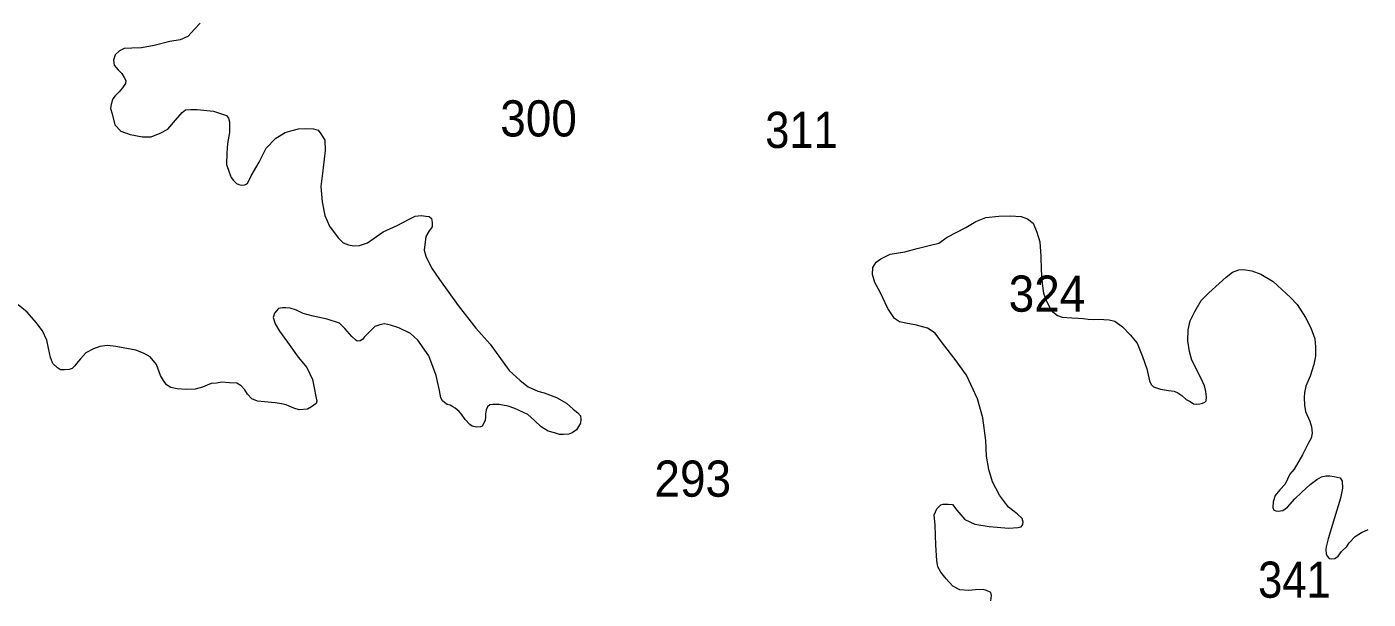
# Model space of a CAD drawing. Extents: x 445.4 to 500, y 8728.7 to 8784.
# Drawn here: x 494.06 to 500, y 8752.65 to 8755.18 of the extents above; entities that cross this region are included whole.
import ezdxf

# ---------------------------------------------------------------- set-up
doc = ezdxf.new("R2010")
doc.units = 0
doc.header["$LTSCALE"] = 0.064
doc.layers.add('2', color=7, linetype='Continuous', lineweight=13)
doc.layers.add('21', color=7, linetype='Continuous')

msp = doc.modelspace()

# ---------------------------------------------------------------- linework, layer by layer
at = {"layer": '2'}
for points in [[(494.8312, 8755.1948), (494.8068, 8755.1685), (494.7766, 8755.1365), (494.7428, 8755.1215), (494.6976, 8755.114), (494.6279, 8755.0971), (494.5727, 8755.0867), (494.5294, 8755.0848), (494.4956, 8755.083), (494.4749, 8755.0736), (494.456, 8755.0548), (494.4485, 8755.0322), (494.4504, 8755.0097), (494.4692, 8754.989), (494.4843, 8754.9721), (494.4956, 8754.9552), (494.5031, 8754.942), (494.5012, 8754.9289), (494.488, 8754.9101), (494.473, 8754.8913), (494.456, 8754.8744), (494.4447, 8754.8613), (494.4372, 8754.8368), (494.4353, 8754.818), (494.4415, 8754.7948), (494.4547, 8754.7459), (494.481, 8754.7177), (494.5224, 8754.7027), (494.577, 8754.6933), (494.6147, 8754.6933), (494.6542, 8754.7083), (494.6881, 8754.7271), (494.7219, 8754.7666), (494.7521, 8754.8004), (494.7671, 8754.8117), (494.7897, 8754.8135), (494.8179, 8754.8135), (494.8913, 8754.806), (494.9214, 8754.7966), (494.9478, 8754.7872), (494.9572, 8754.776), (494.961, 8754.7591), (494.961, 8754.7121), (494.9522, 8754.6626), (494.9503, 8754.6213), (494.9484, 8754.5706), (494.9597, 8754.5367), (494.9691, 8754.5123), (494.9785, 8754.4992), (494.9917, 8754.486), (495.003, 8754.4823), (495.0143, 8754.4785), (495.0293, 8754.4804), (495.0406, 8754.486), (495.0576, 8754.5198), (495.0933, 8754.58), (495.1234, 8754.642), (495.1667, 8754.687), (495.2081, 8754.7115), (495.2382, 8754.7209), (495.2665, 8754.7284), (495.2985, 8754.7303), (495.3324, 8754.7284), (495.3531, 8754.7227), (495.3662, 8754.7058), (495.3832, 8754.6777), (495.3851, 8754.6326), (495.3756, 8754.5555), (495.3662, 8754.4729), (495.3719, 8754.4052), (495.3832, 8754.3451), (495.4046, 8754.2972), (495.4423, 8754.2464), (495.4649, 8754.2239), (495.4874, 8754.2145), (495.5119, 8754.2107), (495.5364, 8754.2126), (495.5721, 8754.2239), (495.6418, 8754.2727), (495.7039, 8754.3009), (495.7566, 8754.3291), (495.783, 8754.3422), (495.8093, 8754.3441), (495.83, 8754.3422), (495.8451, 8754.3404), (495.8545, 8754.331), (495.8582, 8754.3141), (495.8582, 8754.2953), (495.8451, 8754.2765), (495.83, 8754.2521), (495.8225, 8754.1919), (495.83, 8754.1656), (495.8545, 8754.113)], [(498.3303, 8752.6405), (498.3335, 8752.6643), (498.3303, 8752.677), (498.3112, 8752.6866), (498.2969, 8752.6914), (498.2618, 8752.6898), (498.2331, 8752.6866), (498.1933, 8752.6898), (498.1614, 8752.7057), (498.1327, 8752.7375), (498.1088, 8752.7677), (498.0961, 8752.7916), (498.0913, 8752.8186), (498.0865, 8752.887), (498.0845, 8752.9755), (498.0797, 8753.0216), (498.0909, 8753.047), (498.1084, 8753.0645), (498.1196, 8753.0677), (498.1419, 8753.0677), (498.161, 8753.0661), (498.1801, 8753.0423), (498.2152, 8753.0009), (498.2598, 8752.9802), (498.3236, 8752.9691), (498.4096, 8752.9627), (498.4495, 8752.9643), (498.4638, 8752.9675), (498.4718, 8752.9786), (498.4734, 8752.9882), (498.4686, 8753.0041), (498.4463, 8753.0248), (498.408, 8753.055), (498.3682, 8753.1075), (498.3379, 8753.1663), (498.3207, 8753.2213), (498.3111, 8753.2802), (498.3079, 8753.3502), (498.2952, 8753.4504), (498.2713, 8753.5347), (498.2233, 8753.6394), (498.1723, 8753.7078), (498.1165, 8753.7809), (498.0846, 8753.8239), (498.0496, 8753.8461), (498.0017, 8753.8605), (497.9539, 8753.8684), (497.9268, 8753.8748), (497.9045, 8753.8891), (497.8742, 8753.9336), (497.8403, 8754.0063), (497.8164, 8754.0492), (497.8069, 8754.0842), (497.8085, 8754.1145), (497.8228, 8754.1383), (497.8435, 8754.1526), (497.885, 8754.1733), (497.9503, 8754.1845), (498.0045, 8754.1988), (498.0571, 8754.2115), (498.1001, 8754.2226), (498.1368, 8754.2497), (498.2202, 8754.2919), (498.2632, 8754.319), (498.3079, 8754.3365), (498.3652, 8754.3413), (498.4162, 8754.3428), (498.4641, 8754.3397), (498.4927, 8754.3301), (498.5182, 8754.311), (498.5342, 8754.2713), (498.5469, 8754.2283), (498.5517, 8754.1647), (498.5533, 8754.1026), (498.5569, 8754.0442)], [(495.8545, 8754.113), (495.8902, 8754.0623), (495.9737, 8753.9464), (496.0508, 8753.8469), (496.1148, 8753.7755), (496.1995, 8753.659), (496.2469, 8753.6148), (496.2827, 8753.5866), (496.326, 8753.5679), (496.3542, 8753.5603), (496.4088, 8753.5397), (496.4521, 8753.5152), (496.4822, 8753.4889), (496.5029, 8753.472), (496.5142, 8753.4589), (496.5161, 8753.4439), (496.5142, 8753.4269), (496.4973, 8753.3969), (496.4784, 8753.3837), (496.4634, 8753.3781), (496.4389, 8753.3762), (496.422, 8753.3762), (496.3994, 8753.3837), (496.3711, 8753.3912), (496.341, 8753.41), (496.3109, 8753.4382), (496.2808, 8753.4645), (496.2243, 8753.4908), (496.1942, 8753.5021), (496.1543, 8753.5095), (496.126, 8753.5095), (496.1129, 8753.5077), (496.1034, 8753.4983), (496.0978, 8753.4851), (496.094, 8753.4682), (496.094, 8753.4532), (496.0922, 8753.44), (496.0884, 8753.4288), (496.079, 8753.4137), (496.0715, 8753.41), (496.0545, 8753.4081), (496.0357, 8753.4137), (496.0244, 8753.4212), (496.0037, 8753.4419), (495.9886, 8753.4663), (495.9773, 8753.4776), (495.9604, 8753.4926), (495.9491, 8753.4983), (495.9378, 8753.5058), (495.9246, 8753.5095), (495.9133, 8753.5171), (495.9039, 8753.5246), (495.8964, 8753.5377), (495.8908, 8753.5715), (495.8757, 8753.6373), (495.8437, 8753.7237), (495.7948, 8753.7932), (495.7628, 8753.8233), (495.7113, 8753.8487), (495.6737, 8753.8599), (495.6473, 8753.8656), (495.6266, 8753.8618), (495.604, 8753.8543), (495.5833, 8753.8336), (495.557, 8753.8073), (495.5513, 8753.7979), (495.54, 8753.7904), (495.5268, 8753.7885), (495.5193, 8753.7942), (495.5024, 8753.8092), (495.4723, 8753.8449), (495.4478, 8753.8693), (495.3932, 8753.8862), (495.3311, 8753.8994), (495.2878, 8753.9107), (495.2577, 8753.9257), (495.2295, 8753.9351), (495.2106, 8753.937), (495.1956, 8753.937), (495.1786, 8753.9332), (495.1598, 8753.9125), (495.1542, 8753.8937), (495.1636, 8753.8656), (495.1824, 8753.8336), (495.2182, 8753.7848), (495.2652, 8753.719), (495.3029, 8753.672), (495.3292, 8753.6194), (495.3362, 8753.5826), (495.3437, 8753.545), (495.3475, 8753.5243), (495.3456, 8753.513), (495.3249, 8753.498), (495.3061, 8753.4886), (495.2703, 8753.4849), (495.2459, 8753.4924), (495.2252, 8753.5018), (495.212, 8753.5074), (495.1913, 8753.5112), (495.163, 8753.5168), (495.116, 8753.5206)], [(498.5569, 8754.0442), (498.5634, 8754.001), (498.5743, 8753.9739), (498.5966, 8753.9242), (498.6247, 8753.9027), (498.6462, 8753.8953), (498.6884, 8753.8928), (498.7182, 8753.8911), (498.7388, 8753.8895), (498.7603, 8753.887), (498.7851, 8753.8845), (498.8166, 8753.8862), (498.8299, 8753.8852), (498.8546, 8753.8831), (498.8794, 8753.8769), (498.9123, 8753.8522), (498.9474, 8753.8173), (498.9783, 8753.7802), (499.001, 8753.7205), (499.0211, 8753.6671), (499.0329, 8753.6141), (499.0403, 8753.5979), (499.0506, 8753.5875), (499.0639, 8753.5831), (499.0816, 8753.5772), (499.117, 8753.5713), (499.1421, 8753.5684), (499.1584, 8753.561), (499.1761, 8753.5492), (499.1953, 8753.5315), (499.213, 8753.5227), (499.2278, 8753.5124), (499.2425, 8753.5106), (499.2546, 8753.5114), (499.2674, 8753.5146), (499.277, 8753.5194), (499.2834, 8753.5258), (499.285, 8753.5434), (499.281, 8753.5658), (499.2762, 8753.5914), (499.2578, 8753.6291), (499.2201, 8753.7051), (499.2088, 8753.7427), (499.2027, 8753.7909), (499.2042, 8753.8396), (499.213, 8753.8794), (499.2337, 8753.9206), (499.2605, 8753.9689), (499.2945, 8754.0028), (499.3403, 8754.0441), (499.3713, 8754.0721), (499.3993, 8754.0942), (499.4274, 8754.1045), (499.4481, 8754.106), (499.485, 8754.1001), (499.5249, 8754.0854), (499.5795, 8754.0529), (499.6179, 8754.0176), (499.6563, 8753.9822), (499.6858, 8753.9512), (499.7227, 8753.8938), (499.7464, 8753.8481), (499.7645, 8753.7997), (499.7674, 8753.7643), (499.7674, 8753.7231), (499.76, 8753.6862), (499.7438, 8753.6346), (499.7246, 8753.5904), (499.7187, 8753.5624), (499.7172, 8753.5388), (499.7187, 8753.5064), (499.7231, 8753.4784), (499.7424, 8753.4348), (499.7498, 8753.4097), (499.7528, 8753.3817), (499.7483, 8753.3596), (499.735, 8753.336), (499.7099, 8753.2859), (499.673, 8753.2225), (499.6538, 8753.2004), (499.633, 8753.1567), (499.6094, 8753.1316), (499.5887, 8753.1066), (499.5798, 8753.0786), (499.5783, 8753.0535), (499.5828, 8753.0417), (499.5916, 8753.0388), (499.602, 8753.0373), (499.6226, 8753.0402), (499.6433, 8753.055), (499.6758, 8753.0918), (499.7068, 8753.1213), (499.7437, 8753.1552), (499.7733, 8753.1773), (499.794, 8753.1891), (499.8132, 8753.1935), (499.8309, 8753.1935), (499.8501, 8753.1906), (499.8767, 8753.1847), (499.8855, 8753.1699), (499.887, 8753.139)], [(495.116, 8753.5206), (495.0859, 8753.5243), (495.0595, 8753.5337), (495.0407, 8753.5544), (495.0294, 8753.5732), (495.0125, 8753.592), (494.9937, 8753.6032), (494.9617, 8753.6051), (494.9278, 8753.607), (494.9033, 8753.6032), (494.8807, 8753.6013), (494.8619, 8753.5938), (494.8412, 8753.5863), (494.8092, 8753.5769), (494.7697, 8753.575), (494.7301, 8753.5788), (494.7019, 8753.5844), (494.6831, 8753.5957), (494.6699, 8753.6145), (494.6567, 8753.637), (494.6379, 8753.6859), (494.6097, 8753.7197), (494.5815, 8753.7366), (494.5476, 8753.7498), (494.4591, 8753.7648), (494.422, 8753.7695), (494.3882, 8753.7657), (494.3599, 8753.7545), (494.326, 8753.7376), (494.3016, 8753.7112), (494.2846, 8753.6906), (494.2771, 8753.6793), (494.2658, 8753.668), (494.2526, 8753.6643), (494.2319, 8753.6624), (494.2131, 8753.6624), (494.1999, 8753.6718), (494.1792, 8753.6906), (494.1698, 8753.7169), (494.1604, 8753.7582), (494.1529, 8753.7939), (494.1341, 8753.8352), (494.1058, 8753.8709), (494.0663, 8753.9179), (494.0268, 8753.9499)], [(499.887, 8753.139), (499.8781, 8753.0948), (499.8515, 8753.0078), (499.8235, 8752.915), (499.8136, 8752.879), (499.8122, 8752.8672), (499.8136, 8752.8466), (499.8196, 8752.8363), (499.8269, 8752.8274), (499.8388, 8752.826), (499.852, 8752.8274), (499.8668, 8752.8377), (499.8816, 8752.8584), (499.9052, 8752.8805), (499.9155, 8752.8967), (499.9421, 8752.9247), (499.9702, 8752.9424), (500, 8752.9561)]]:
    msp.add_lwpolyline(points, dxfattribs=at)

# ---------------------------------------------------------------- texts
at = {"layer": '21'}
for s, width, p in [('300', 0.95, (496.1594, 8754.6943)), ('311', 0.9, (497.3319, 8754.6434)), ('324', 0.95, (498.4092, 8753.9193)), ('293', 0.95, (496.8417, 8753.1011)), ('341', 0.9, (499.5129, 8752.6543))]:
    msp.add_text(s, height=0.16, dxfattribs=dict(at, width=width)).set_placement(p)

doc.saveas('drawing.dxf')
